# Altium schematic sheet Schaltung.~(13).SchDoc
size A4
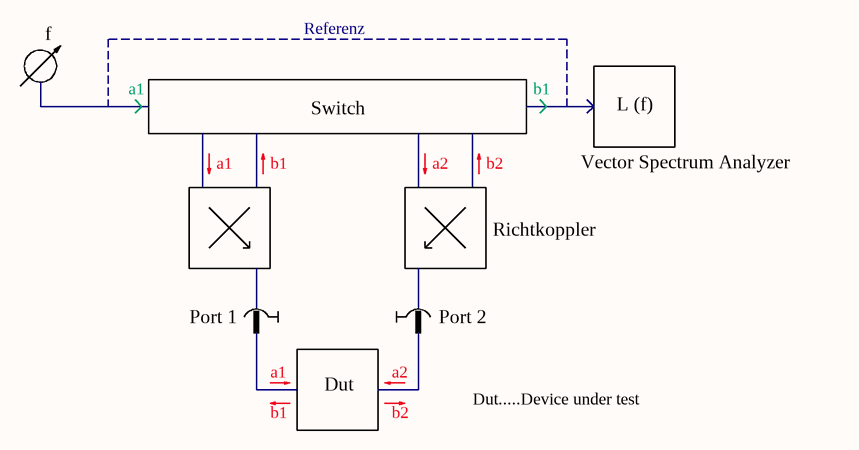
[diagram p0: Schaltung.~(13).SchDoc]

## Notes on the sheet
- f
- Referenz
- a1
- Switch
- b1
- L (f)
- a2
- b2
- Vector Spectrum Analyzer
- Richtkoppler
- Port 1
- Port 2
- Dut
- Dut.....Device under test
